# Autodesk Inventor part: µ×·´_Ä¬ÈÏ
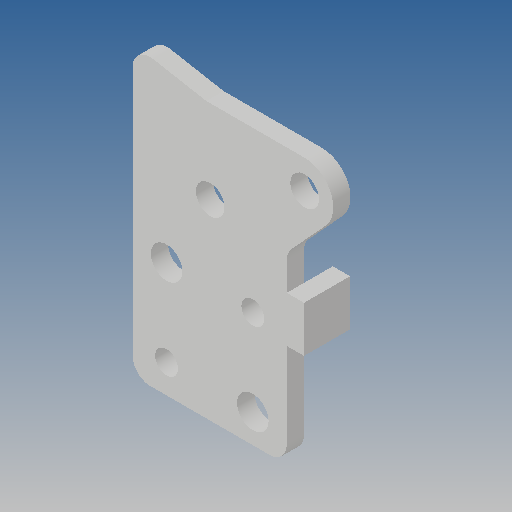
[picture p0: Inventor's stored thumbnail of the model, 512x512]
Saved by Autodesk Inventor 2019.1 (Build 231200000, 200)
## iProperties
Created: 2012-10
Part Number: µ×·´_Ä¬ÈÏ
Material: Ogólny
Document SubType Name: Modeling
Designer: CADENGINEERING4
Density: 1 g/cm^3
Appearance: Domyślna
Author: CADENGINEERING4
Revision Number: ÈÎºÎ
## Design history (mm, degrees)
feature "NONE"
node "Bryła1"
